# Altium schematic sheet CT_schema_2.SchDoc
size 287 x 169 mm
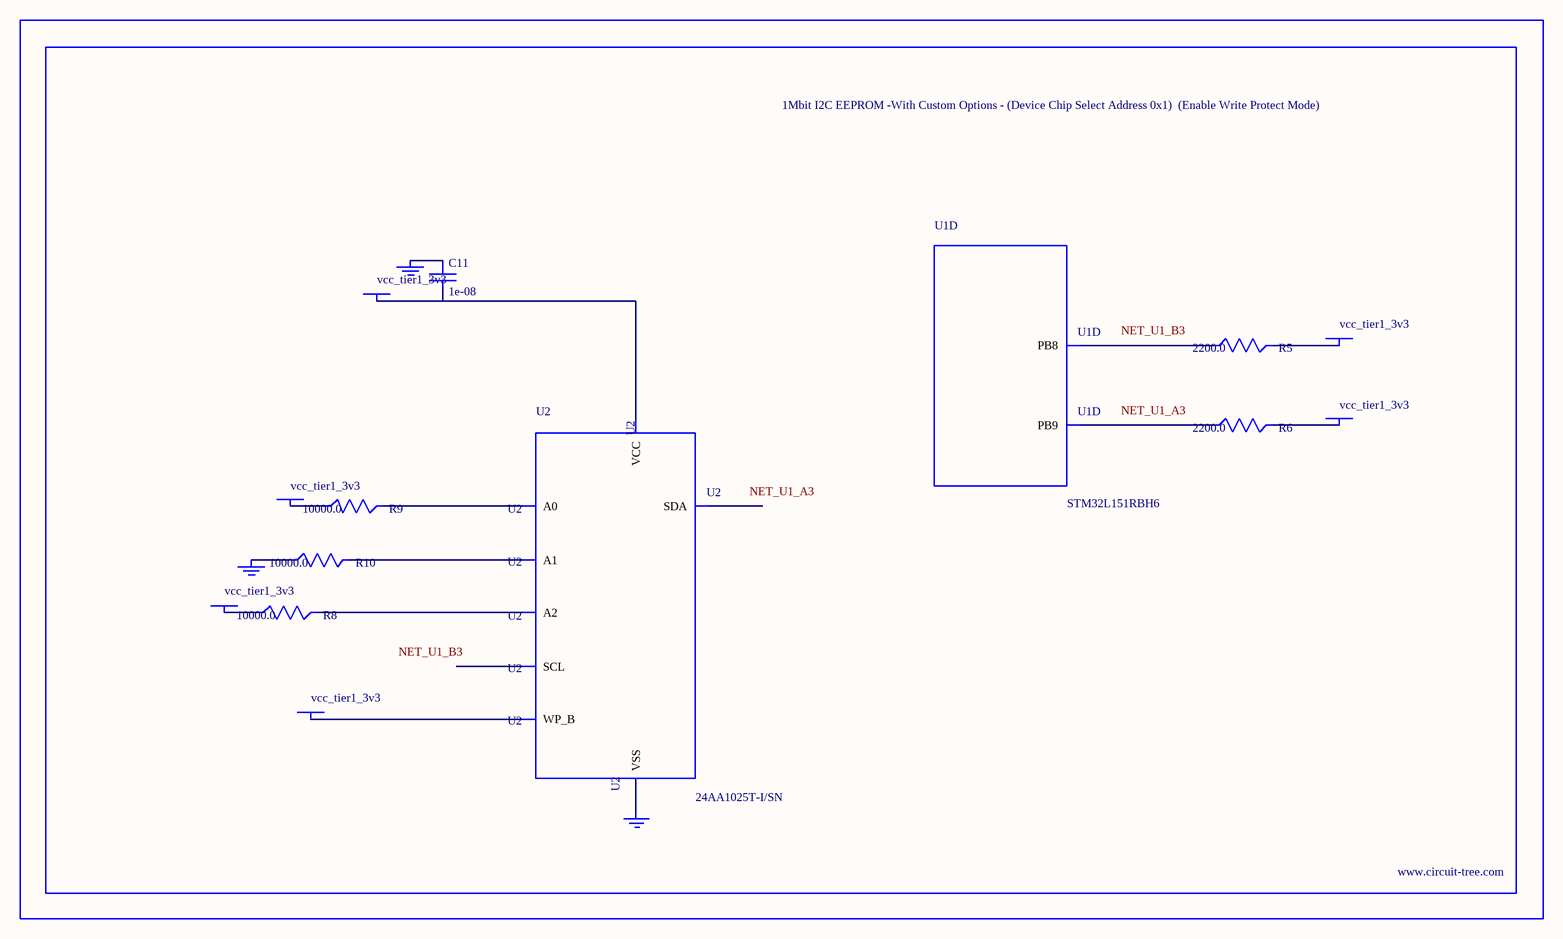
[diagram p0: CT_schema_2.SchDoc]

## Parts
BORDER1  (no value)
C11  1e-08  [C0402]
GND_INSTANCE_1_0  (no value)
GND_INSTANCE_1_1  (no value)
GND_INSTANCE_1_2  (no value)
POWER_INSTANCE_1_0  vcc_tier1_3v3
POWER_INSTANCE_1_1  vcc_tier1_3v3
POWER_INSTANCE_1_2  vcc_tier1_3v3
POWER_INSTANCE_1_3  vcc_tier1_3v3
POWER_INSTANCE_1_4  vcc_tier1_3v3
POWER_INSTANCE_1_5  vcc_tier1_3v3
R5  2200.0  [R0603]
R6  2200.0  [R0603]
R8  10000.0  [R0603]
R9  10000.0  [R0603]
R10  10000.0  [R0603]
U1  STM32L151RBH6  [TFBGA64]  (part D of 6)
U2  24AA1025T-I/SN  [SOIC-8]

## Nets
NetC11_1: C11.1 GND_INSTANCE_1_1.0(GND)
NetC11_2: C11.2 POWER_INSTANCE_1_3.0(PWR) U2.8(VCC)
NetGND_INSTANCE_1_0_0: GND_INSTANCE_1_0.0(GND) R10.1
NetGND_INSTANCE_1_2_0: GND_INSTANCE_1_2.0(GND) U2.4(VSS)
NetPOWER_INSTANCE_1_0_0: POWER_INSTANCE_1_0.0(PWR) R9.1
NetPOWER_INSTANCE_1_1_0: POWER_INSTANCE_1_1.0(PWR) R8.1
NetPOWER_INSTANCE_1_2_0: POWER_INSTANCE_1_2.0(PWR) U2.7(WP_B)
NetPOWER_INSTANCE_1_4_0: POWER_INSTANCE_1_4.0(PWR) R5.2
NetPOWER_INSTANCE_1_5_0: POWER_INSTANCE_1_5.0(PWR) R6.2
NetR5_1: R5.1 U1.B3(PB8)
NetR6_1: R6.1 U1.A3(PB9)
NetR8_2: R8.2 U2.3(A2)
NetR9_2: R9.2 U2.1(A0)
NetR10_2: R10.2 U2.2(A1)

Not connected (* = marked no-connect by the designer): U2 5(SDA) 6(SCL)

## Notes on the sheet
- Labels drawn without touching a wire or pin: NET_U1_A3, NET_U1_B3

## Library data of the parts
BORDER1 = BORDER_PAGE1
C11 = C0402C103K3RAC
GND_INSTANCE_1_0-GND_INSTANCE_1_2 = GND
POWER_INSTANCE_1_0-POWER_INSTANCE_1_5 = PWR
R5 R6 = RC0603JR-072K2L
R8-R10 = RC0603JR-0710KL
